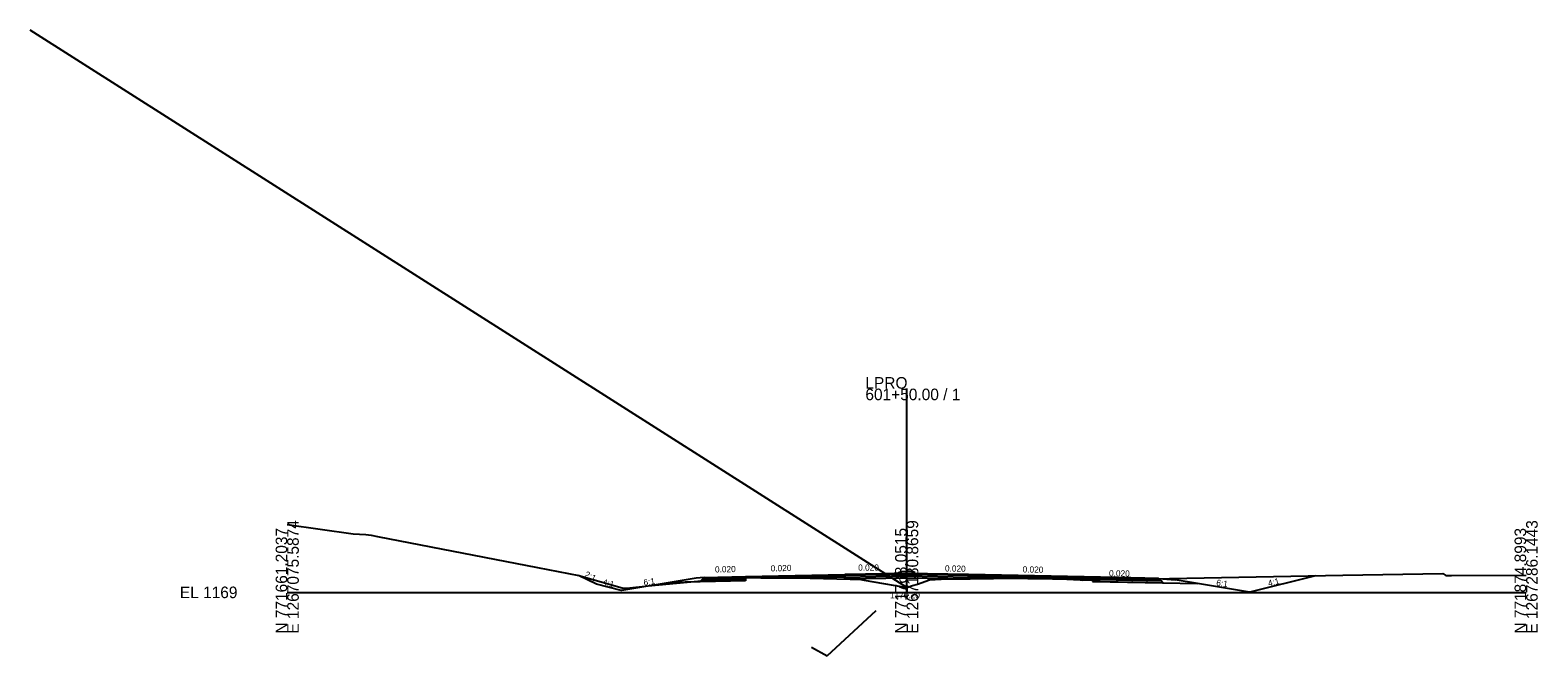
# Model space of a CAD drawing. Extents: x -3833 to 1267678, y -522 to 773248.
# Drawn here: x 937.8 to 1302.8, y 2484.6 to 2636.3 of the extents above; entities that cross this region are included whole.
import ezdxf

# ---------------------------------------------------------------- set-up
doc = ezdxf.new("R2010")
doc.units = 0
for name, color, linetype in [('Exist Cross Section Cell', 7, 'Continuous'), ('Exist XS Center Line Elevation Label', 7, 'Continuous'), ('Exist XS Ground Line', 7, 'Continuous'), ('Prop CMT DNC', 7, 'Continuous'), ('Prop CMT Pvmt Course 1', 7, 'Continuous'), ('Prop CMT Pvmt Course 2', 7, 'Continuous'), ('Prop CMT Pvmt Course 4', 7, 'Continuous'), ('Prop CMT Shld Paved Course 1', 7, 'Continuous'), ('Prop CMT Shld Paved Course 2', 7, 'Continuous'), ('Prop CMT Shld Paved Course 4', 7, 'Continuous'), ('Prop CMT Slope Grass', 7, 'Continuous'), ('Prop CMT Subgrade Earthwork', 7, 'Continuous'), ('Prop Conc Curb and Gutter', 7, 'Continuous'), ('Prop Corridor Mesh Bottom', 7, 'Continuous'), ('Prop XS Ditch Slope Text', 7, 'Continuous'), ('Prop XS Finish Grade', 7, 'Continuous'), ('Prop XS SE Text', 7, 'Continuous'), ('Scratch_Level_1', 7, 'Continuous'), ('Scratch_Level_5', 7, 'Continuous')]:
    doc.layers.add(name, color=color, linetype=linetype)

msp = doc.modelspace()

# ---------------------------------------------------------------- linework, layer by layer
at = {"layer": 'Exist Cross Section Cell'}
for p, q in [((1150, 2500), (1150, 2549.37)), ((1000, 2500), (1150, 2500)), ((1150, 2500), (1300, 2500))]:
    msp.add_line(p, q, dxfattribs=at)
at = {"layer": 'Exist XS Ground Line'}
for p, q in [((1000, 2516.46), (1016, 2514.18)), ((1016, 2514.18), (1019.05, 2514.01)), ((1019.05, 2514.01), (1020.34, 2513.84)), ((1020.34, 2513.84), (1021.9, 2513.54)), ((1021.9, 2513.54), (1060.64, 2506.03)), ((1060.64, 2506.03), (1070.64, 2504.11)), ((1255.6, 2504.16), (1279.87, 2504.61)), ((1279.87, 2504.61), (1280.59, 2504.11)), ((1070.64, 2504.11), (1070.94, 2504.01)), ((1070.94, 2504.01), (1081.36, 2501)), ((1081.36, 2501), (1082.98, 2501.09)), ((1082.98, 2501.09), (1087.44, 2501.58)), ((1087.44, 2501.58), (1106.32, 2503.36)), ((1106.32, 2503.36), (1107.59, 2503.42)), ((1107.59, 2503.42), (1111.59, 2503.59)), ((1111.59, 2503.59), (1114.66, 2503.56)), ((1114.66, 2503.56), (1123.11, 2503.48)), ((1123.11, 2503.48), (1126.67, 2503.41)), ((1126.67, 2503.41), (1136.31, 2503.21)), ((1136.31, 2503.21), (1137.05, 2503.19)), ((1137.05, 2503.19), (1138.91, 2503.13)), ((1138.91, 2503.13), (1139.7, 2502.94)), ((1139.7, 2502.94), (1144.41, 2502.12)), ((1144.41, 2502.12), (1150.07, 2501.18)), ((1150.07, 2501.18), (1151.44, 2501.66)), ((1151.44, 2501.66), (1152.63, 2502.02)), ((1152.63, 2502.02), (1155.54, 2503.07)), ((1155.54, 2503.07), (1158.38, 2503.17)), ((1158.38, 2503.17), (1164.97, 2503.3)), ((1164.97, 2503.3), (1165.35, 2503.31)), ((1165.35, 2503.31), (1176.7, 2503.44)), ((1176.7, 2503.44), (1177.57, 2503.42)), ((1177.57, 2503.42), (1179.36, 2503.38)), ((1179.36, 2503.38), (1185.35, 2503.26)), ((1185.35, 2503.26), (1188.78, 2503.19)), ((1188.78, 2503.19), (1192.03, 2503)), ((1192.03, 2503), (1192.69, 2502.96)), ((1192.69, 2502.96), (1255.6, 2504.16)), ((1280.59, 2504.11), (1281.97, 2504.06)), ((1281.97, 2504.06), (1300, 2504.19))]:
    msp.add_line(p, q, dxfattribs=at)
at = {"layer": 'Prop CMT Pvmt Course 1'}
for p, q in [((1147.75, 2504.55), (1147, 2504.54)), ((1152.25, 2504.55), (1152.82, 2504.54)), ((1152.82, 2504.54), (1153, 2504.54)), ((1111, 2503.82), (1135, 2504.3)), ((1111, 2503.56), (1111, 2503.82)), ((1111, 2503.82), (1111, 2503.82)), ((1135, 2504.3), (1135, 2504.3)), ((1135, 2504.3), (1135, 2504.3)), ((1135, 2504.3), (1135, 2504.05)), ((1135, 2504.05), (1135, 2504.05)), ((1147, 2504.29), (1147.75, 2504.3)), ((1152.82, 2504.29), (1152.25, 2504.3)), ((1153, 2504.29), (1152.82, 2504.29)), ((1201, 2503.58), (1165, 2504.3)), ((1165, 2504.3), (1165, 2504.3)), ((1165, 2504.3), (1165, 2504.3)), ((1165, 2504.3), (1165, 2504.05)), ((1165, 2504.05), (1195, 2503.45)), ((1165, 2504.05), (1165, 2504.05)), ((1195, 2503.7), (1195, 2503.45)), ((1201, 2503.58), (1195, 2503.7)), ((1195, 2503.45), (1195, 2503.7)), ((1195, 2503.7), (1195, 2503.7)), ((1195, 2503.7), (1195, 2503.7)), ((1195, 2503.7), (1201, 2503.58)), ((1195, 2503.45), (1201, 2503.33)), ((1201, 2503.33), (1201, 2503.58))]:
    msp.add_line(p, q, dxfattribs=at)
at = {"layer": 'Prop CMT Pvmt Course 2'}
for p, q in [((1150, 2504.35), (1135, 2504.05)), ((1135, 2504.05), (1135, 2504.05)), ((1135, 2504.05), (1135, 2503.72)), ((1135, 2503.71), (1150, 2504.02)), ((1135, 2503.72), (1135, 2503.71)), ((1147.75, 2504.3), (1147, 2504.29)), ((1165, 2504.05), (1150, 2504.35)), ((1150, 2504.35), (1150, 2504.35)), ((1150, 2504.35), (1150, 2504.35)), ((1150, 2504.02), (1150, 2504.02)), ((1150, 2504.02), (1150, 2504.02)), ((1150, 2504.02), (1165, 2503.71)), ((1152.25, 2504.3), (1152.82, 2504.29)), ((1152.82, 2504.29), (1153, 2504.29)), ((1165, 2503.71), (1165, 2504.05)), ((1165, 2504.05), (1165, 2504.05)), ((1165, 2503.71), (1165, 2503.71)), ((1195, 2503.45), (1195, 2503.12)), ((1201, 2503.33), (1195, 2503.45)), ((1195, 2503.12), (1201, 2503)), ((1201, 2503), (1201, 2503.33))]:
    msp.add_line(p, q, dxfattribs=at)
at = {"layer": 'Prop CMT Pvmt Course 4'}
for p, q in [((1147.98, 2504.56), (1147.98, 2503.52)), ((1151.98, 2504.56), (1151.98, 2503.52)), ((1135, 2503.26), (1135, 2503.72)), ((1135, 2503.72), (1135, 2503.72)), ((1135, 2503.72), (1135, 2503.71)), ((1150, 2504.02), (1150, 2504.02)), ((1150, 2504.02), (1150, 2504.02)), ((1165, 2503.71), (1165, 2503.71)), ((1165, 2503.71), (1165, 2503.71)), ((1165, 2503.71), (1165, 2503.26)), ((1195, 2503.12), (1195, 2502.66)), ((1201, 2503), (1195, 2503.12)), ((1195, 2502.66), (1201, 2502.54)), ((1201, 2502.54), (1201, 2503))]:
    msp.add_line(p, q, dxfattribs=at)
at = {"layer": 'Prop CMT Shld Paved Course 1'}
for p, q in [((1150, 2504.6), (1135, 2504.3)), ((1149.97, 2504.69), (1149.97, 2504.69)), ((1149.97, 2504.69), (1149.97, 2504.69)), ((1165, 2504.3), (1150, 2504.6)), ((1150, 2504.6), (1150, 2504.6)), ((1150, 2504.6), (1150, 2504.6)), ((1100.74, 2503.36), (1101, 2503.62)), ((1111, 2503.57), (1100.74, 2503.36)), ((1101, 2503.62), (1111, 2503.82)), ((1101, 2503.62), (1101, 2503.62)), ((1111, 2503.82), (1111, 2503.82)), ((1111, 2503.82), (1111, 2503.82)), ((1111, 2503.82), (1111, 2503.57)), ((1111, 2503.57), (1111, 2503.57)), ((1135, 2504.3), (1135, 2504.3)), ((1135, 2504.3), (1135, 2504.05)), ((1149.97, 2504.44), (1149.97, 2504.44)), ((1150, 2504.35), (1150, 2504.35)), ((1150, 2504.35), (1150, 2504.35)), ((1165, 2504.05), (1165, 2504.3)), ((1165, 2504.3), (1165, 2504.3)), ((1201, 2503.58), (1201, 2503.33)), ((1211, 2503.38), (1201, 2503.58)), ((1201, 2503.33), (1211.26, 2503.12)), ((1211.26, 2503.12), (1211, 2503.38))]:
    msp.add_line(p, q, dxfattribs=at)
at = {"layer": 'Prop CMT Shld Paved Course 2'}
for p, q in [((1100.4, 2503.02), (1100.74, 2503.36)), ((1100.74, 2503.36), (1100.74, 2503.36)), ((1111, 2503.57), (1111, 2503.57)), ((1111, 2503.57), (1111, 2503.57)), ((1111, 2503.23), (1111, 2503.23)), ((1111.14, 2503.57), (1111.14, 2503.57)), ((1111.59, 2503.58), (1111.59, 2503.58)), ((1111.96, 2503.59), (1123.1, 2503.81)), ((1111.96, 2503.59), (1111.96, 2503.59)), ((1114.65, 2503.64), (1114.65, 2503.64)), ((1114.65, 2503.56), (1114.65, 2503.56)), ((1123.1, 2503.81), (1126.67, 2503.88)), ((1123.1, 2503.81), (1123.1, 2503.81)), ((1123.27, 2503.48), (1123.1, 2503.48)), ((1123.1, 2503.48), (1123.1, 2503.48)), ((1126.67, 2503.55), (1123.27, 2503.48)), ((1123.27, 2503.48), (1123.27, 2503.48)), ((1126.67, 2503.88), (1135, 2504.05)), ((1126.67, 2503.88), (1126.67, 2503.88)), ((1135, 2503.71), (1126.67, 2503.55)), ((1126.67, 2503.55), (1126.67, 2503.55)), ((1135, 2504.05), (1135, 2504.05)), ((1135, 2504.05), (1135, 2504.05)), ((1135, 2504.05), (1135, 2503.71)), ((1135, 2503.71), (1135, 2503.71)), ((1165.35, 2504.04), (1165, 2504.05)), ((1165, 2504.05), (1165, 2504.05)), ((1165, 2504.05), (1165, 2503.71)), ((1165, 2503.71), (1165.35, 2503.71)), ((1176.7, 2503.81), (1165.35, 2504.04)), ((1165.35, 2504.04), (1165.35, 2504.04)), ((1165.35, 2503.71), (1165.35, 2503.71)), ((1165.35, 2503.71), (1176.7, 2503.48)), ((1177.56, 2503.8), (1176.7, 2503.81)), ((1176.7, 2503.81), (1176.7, 2503.81)), ((1176.7, 2503.48), (1176.7, 2503.48)), ((1176.7, 2503.48), (1177.56, 2503.46)), ((1179.36, 2503.76), (1177.56, 2503.8)), ((1177.56, 2503.46), (1179.36, 2503.43)), ((1185.35, 2503.64), (1179.36, 2503.76)), ((1179.36, 2503.76), (1179.36, 2503.76)), ((1179.36, 2503.43), (1179.36, 2503.43)), ((1179.36, 2503.43), (1185.35, 2503.31)), ((1188.78, 2503.57), (1185.35, 2503.64)), ((1185.35, 2503.64), (1185.35, 2503.64)), ((1185.35, 2503.31), (1185.35, 2503.31)), ((1185.35, 2503.31), (1188.78, 2503.24)), ((1192.03, 2503.51), (1188.78, 2503.57)), ((1188.78, 2503.57), (1188.78, 2503.57)), ((1188.78, 2503.24), (1188.78, 2503.24)), ((1188.78, 2503.24), (1192.03, 2503.17)), ((1192.69, 2503.49), (1192.03, 2503.51)), ((1192.03, 2503.51), (1192.03, 2503.51)), ((1192.03, 2503.17), (1192.03, 2503.17)), ((1192.03, 2503.17), (1192.69, 2503.16)), ((1195, 2503.45), (1192.69, 2503.49)), ((1192.69, 2503.49), (1192.69, 2503.49)), ((1192.69, 2503.16), (1192.69, 2503.16)), ((1192.69, 2503.16), (1195, 2503.11)), ((1195, 2503.11), (1195, 2503.45)), ((1195, 2503.45), (1195, 2503.45)), ((1201, 2503.33), (1201, 2503)), ((1211.26, 2503.12), (1201, 2503.33)), ((1201, 2503), (1211.59, 2502.79)), ((1211.59, 2502.79), (1211.26, 2503.12))]:
    msp.add_line(p, q, dxfattribs=at)
at = {"layer": 'Prop CMT Shld Paved Course 4'}
for p, q in [((1099.94, 2502.55), (1100.4, 2503.02)), ((1100.4, 2503.02), (1100.9, 2503.03)), ((1100.9, 2503.03), (1111, 2503.23)), ((1201, 2503), (1201, 2502.54)), ((1211.09, 2502.8), (1201, 2503)), ((1201, 2502.54), (1212.06, 2502.32)), ((1211.59, 2502.79), (1211.09, 2502.8)), ((1212.06, 2502.32), (1211.59, 2502.79))]:
    msp.add_line(p, q, dxfattribs=at)
at = {"layer": 'Prop CMT Slope Grass'}
for p, q in [((1099, 2503.46), (1092.72, 2502.41)), ((1101, 2503.62), (1099, 2503.46)), ((1211, 2503.38), (1215, 2503.06)), ((1220.43, 2502.15), (1215, 2503.06))]:
    msp.add_line(p, q, dxfattribs=at)
at = {"layer": 'Prop CMT Subgrade Earthwork'}
for p, q in [((1110.99, 2502.78), (1092.72, 2502.41)), ((1111, 2503.56), (1110.99, 2502.78)), ((1135, 2503.26), (1149.99, 2503.56)), ((1135, 2503.26), (1135, 2503.24)), ((1149.99, 2503.56), (1165, 2503.26)), ((1165, 2503.3), (1165, 2503.26)), ((1195, 2503), (1195, 2502.66)), ((1195, 2502.66), (1220.43, 2502.15))]:
    msp.add_line(p, q, dxfattribs=at)
at = {"layer": 'Prop Conc Curb and Gutter'}
for p, q in [((1147.98, 2504.67), (1147.99, 2504.84)), ((1147.98, 2504.67), (1147.98, 2504.54)), ((1147.98, 2504.54), (1149.98, 2504.54)), ((1147.99, 2504.84), (1148.74, 2505.09)), ((1148.74, 2505.09), (1149.98, 2505.11)), ((1151.22, 2505.08), (1149.98, 2505.11)), ((1151.98, 2504.54), (1149.98, 2504.54)), ((1151.97, 2504.83), (1151.22, 2505.08)), ((1151.98, 2504.67), (1151.97, 2504.83)), ((1151.98, 2504.67), (1151.98, 2504.54))]:
    msp.add_line(p, q, dxfattribs=at)
at = {"layer": 'Prop Corridor Mesh Bottom'}
for p, q in [((1111, 2503.82), (1111, 2503.57)), ((1135, 2504.3), (1135, 2504.05)), ((1165, 2504.3), (1165, 2504.05)), ((1201, 2503.58), (1201, 2503.33))]:
    msp.add_line(p, q, dxfattribs=at)
at = {"layer": 'Prop XS Finish Grade'}
for p, q in [((1074.9, 2501.96), (1070.57, 2504.12)), ((1080.9, 2500.46), (1074.9, 2501.96)), ((1092.72, 2502.41), (1081, 2500.46)), ((1215, 2503.06), (1215, 2503.06)), ((1233, 2500.06), (1220.43, 2502.15)), ((1249.01, 2504.03), (1233.1, 2500.06)), ((1080.95, 2500.46), (1080.9, 2500.46)), ((1081, 2500.46), (1080.95, 2500.46)), ((1233.05, 2500.06), (1233, 2500.06)), ((1233.1, 2500.06), (1233.05, 2500.06)), ((1233.05, 2500.06), (1233.05, 2500.06)), ((1233.05, 2500.06), (1233.05, 2500.06)), ((1233.1, 2500.06), (1233.1, 2500.06))]:
    msp.add_line(p, q, dxfattribs=at)
at = {"layer": 'Scratch_Level_1'}
msp.add_line((1150, 2501.2), (937.75, 2636.25), dxfattribs=at)
at = {"layer": 'Scratch_Level_5'}
for p, q in [((1130.72, 2484.61), (1142.58, 2495.63)), ((1126.94, 2486.71), (1130.72, 2484.61))]:
    msp.add_line(p, q, dxfattribs=at)

# ---------------------------------------------------------------- texts
at = {"layer": 'Exist Cross Section Cell'}
for s, p in [('LPRO', (1140, 2549.37)), ('601+50.00 / 1', (1140, 2546.57)), ('EL 1169', (974, 2498.6))]:
    msp.add_text(s, height=2.8, dxfattribs=at).set_placement(p)
for s, p in [('E 1267075.5874', (1002.8, 2490)), ('E 1267180.8659', (1152.8, 2490)), ('E 1267286.1443', (1302.8, 2490)), ('N 771661.2037', (1000, 2490)), ('N 771768.0515', (1150, 2490)), ('N 771874.8993', (1300, 2490))]:
    msp.add_text(s, height=2.8, rotation=90, dxfattribs=at).set_placement(p)
at = {"layer": 'Exist XS Center Line Elevation Label'}
msp.add_text('1170.20', height=1.5, dxfattribs=at).set_placement((1145.96, 2498.55))
at = {"layer": 'Prop CMT DNC'}
for p in [(1066.8, 2504.85), (1149.97, 2504.69), (1150, 2504.6), (1101, 2503.62), (1111, 2503.82), (1111, 2503.82), (1135, 2504.3), (1135, 2504.3), (1165, 2504.3), (1165, 2504.3), (1201, 2503.58), (1201, 2503.58), (1211, 2503.38), (1249.01, 2504.03), (1080.95, 2500.46), (1081, 2500.46), (1233, 2500.06), (1233.05, 2500.06)]:
    msp.add_text('X', height=0.00025, dxfattribs=at).set_placement(p)
at = {"layer": 'Prop XS Ditch Slope Text'}
for s, rotation, p in [('2:1', 334.1731, (1071.87, 2503.85)), ('4:1', 343.7547, (1076.23, 2501.89)), ('6:1', 9.0286, (1086.39, 2501.61)), ('6:1', 352.0901, (1224.9, 2501.64)), ('4:1', 14.1789, (1237.69, 2501.41))]:
    msp.add_text(s, height=1.5, rotation=rotation, dxfattribs=at).set_placement(p)
at = {"layer": 'Prop XS SE Text'}
for rotation, p in [(1.397, (1103.6, 2504.8)), (1.397, (1117.09, 2505.06)), (0.2693, (1138.26, 2505.25)), (358.8542, (1159.26, 2505.07)), (358.8542, (1178.07, 2504.83)), (358.8542, (1198.99, 2503.91))]:
    msp.add_text('0.020', height=1.5, rotation=rotation, dxfattribs=at).set_placement(p)

doc.saveas('drawing.dxf')
